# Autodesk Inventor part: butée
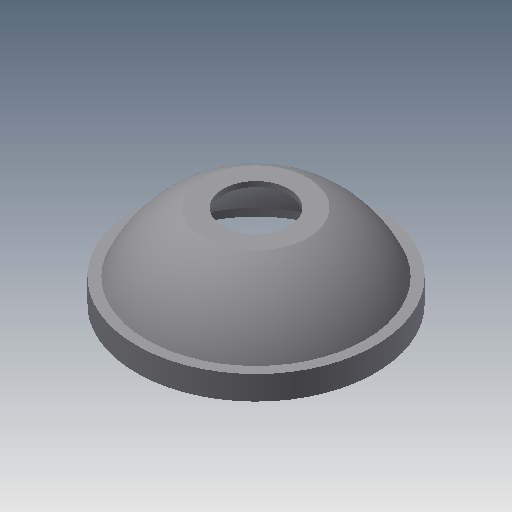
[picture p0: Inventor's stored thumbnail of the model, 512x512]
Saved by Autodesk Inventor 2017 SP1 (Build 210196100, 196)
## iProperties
Shininess: 64.0
Length Units: 11269
Angle Units: 11279
Time Units: 11290
Mass Units: 11283
Length Display Precision: 3
Angle Display Precision: 2
Compacted: True
Part Number: butée
Document SubType Name: Modeling
Created: 2003-07
Material: Générique
Designer: trameau
Mass: 0.451507 g
Surface Area: 9.92923 cm^2
Volume: 0.451507 cm^3
Density: 1 g/cm^3
Appearance: Par défaut
Density: 0.0
Volumn: 0.0
Area: 0.0
PropertySet Name: Model Information
Control State: 0
Master: False
Checked Out: False
Author: trameau
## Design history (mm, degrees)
sketch "Esquisse1"
  geometry: L1 (5.067, 5.018)-(5.067, 3.018); L2 (5.067, 3.018)-(-14.933, 3.018); L3 (-14.933, 3.018)-(-14.933, 5.018); L4 (-9.292, 10.018)-(-0.575, 10.018); L5 (-4.933, 3.018)-(-4.933, 10.018); L6 (-14.933, 5.018)-(-4.933, 5.018); L7 (4.232, 5.018)-(5.067, 5.018); A1 r 10 centre (-4.933, 1.018) between (4.232, 5.018) and (-0.575, 10.018); A2 r 10 centre (-4.933, 1.018) between (-9.292, 10.018) and (-14.099, 5.018)
  constraints: 14 end point, 4 perpendicular, 4 point on circle, 3 parallel, 2 centre point, 2 horizontal, 2 midpoint, 2 point on line
  dimensions: "d1" = 9 distance from line of A1.centre L4; "d2" = 2 distance of L2.end L3.end; "d3" = 20 distance of L3.end L1.start; "d4" = 2 distance from line of A1.centre L2; "d5" = 10 distance from line of A1.centre L3 (= 0.5 x d3)
revolve "Révolution1" sketch "Esquisse1" stored, may be unused: angle "d6" = 90 deg
feature "Coque2" dims "d8" = 1
sketch "Esquisse2"
  geometry: C1 r 4.359 at (0, 0) reference; C2 r 2.75 at (0, 0); 1 further point
  constraints: 1 centre point
  dimensions: "d9" = 5.5 diameter of C2
extrude "Extrusion1" cut sketch "Esquisse2" stored distance "d10" = 10; taper "d11" = 0 deg
node "Solide1"
node "Corps solides"
node "Corps surfaciques"
